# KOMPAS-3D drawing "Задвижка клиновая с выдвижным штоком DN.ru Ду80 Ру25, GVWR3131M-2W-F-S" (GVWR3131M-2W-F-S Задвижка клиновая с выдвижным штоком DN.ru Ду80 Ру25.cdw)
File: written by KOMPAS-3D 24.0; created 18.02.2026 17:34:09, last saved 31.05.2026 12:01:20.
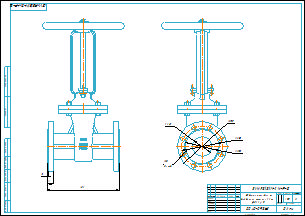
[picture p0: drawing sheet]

Document properties: art: D040-08596; Автор: R2D2; Форматы листов документа: A2; Полное имя файла: GVWR3131M-2W-F-S Задвижка клиновая с выдвижным штоком DN.ru Ду80 Ру25.m3d; Масса: 25.5; Наименование: Задвижка клиновая с выдвижным штоком DN.ru Ду80 Ру25; Количество листов документа: 1; Примечание: D040-09368

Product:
- Part/product: Задвижка клиновая с выдвижным штоком DN.ru Ду80 Ру25  | designation GVWR3131M-2W-F-S
    Масса: 25.5
    Раздел спецификации: Прочие изделия
    Примечание: D040-09368

Views: Вид 1, Справа
Referenced files in E:\Работа\Зайцев\GVWR3131M-2W-F-S Задвижка клиновая с выдвижным штоком DN.ru Ду50-200 Ру63\DN80\: GVWR3131M-2W-F-S Задвижка клиновая с выдвижным штоком DN.ru Ду80 Ру63.m3d
Referenced files in E:\Работа\Зайцев\GVWR3131M-2W-F-S Задвижка клиновая 30нж64нж DN.ru  Ду50-150 Ру25\исходные данные\DN80\dn80\: GVWR3131M-2W-F-S Задвижка клиновая с выдвижным штоком DN.ru Ду80 Ру25.m3d
Referenced files in E:\Работа\Зайцев\Для компаса\: чертеж DN.ru А3.cdt
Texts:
  GVWR3131M-2W-F-S
  чертеж DN.ru А3.cdt
  Задвижка клиновая с
  выдвижным штоком DN.ru
  Ду80 Ру25
  Задвижка клиновая с выдвижным штоком DN.ru Ду80 Ру25
  GVWR3131M-2W-F-S Задвижка клиновая с выдвижным штоком DN.ru Ду80 Ру25
Dimensions and other numbers on the sheet: 0; 3; 2; 4; 280; 22; 1:2; 1; 25,5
